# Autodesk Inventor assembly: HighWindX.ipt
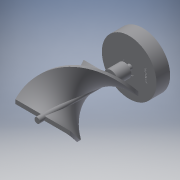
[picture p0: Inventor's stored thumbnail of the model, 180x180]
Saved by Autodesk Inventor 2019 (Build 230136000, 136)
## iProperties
Created: 2018-12
Part Number: HighWindX.ipt
Document SubType Name: Assembly
Designer: Patel Family
Author: Patel Family
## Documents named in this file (3)
- A:\Documents\Inventor Files\HighWindX.ipt.iam
- A:\Documents\Inventor Files\HighWindX Blade.ipt
- A:\Documents\Inventor Files\HighWindX Motor.ipt
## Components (2 placed, 2 different names)
1. HighWindX Blade:1 — Insert:1
2. HighWindX Motor:1 — Insert:1
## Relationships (1: Insert 1)
- Insert:1: HighWindX Blade:1 ↔ HighWindX Motor:1
